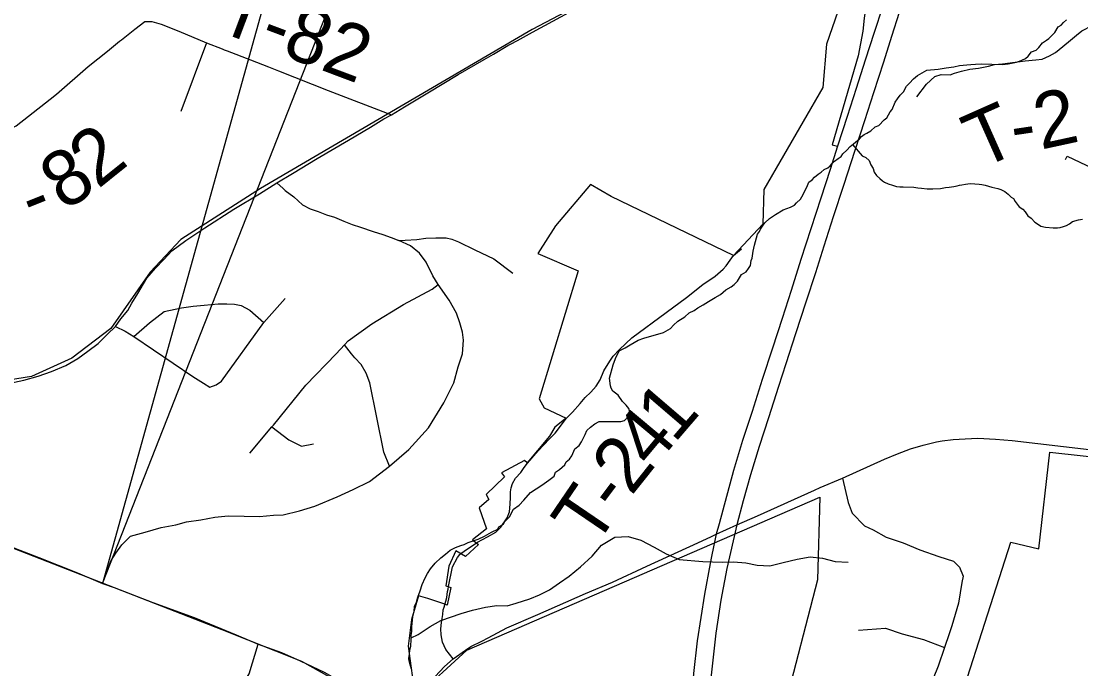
# Model space of a CAD drawing. Extents: x 44.2 to 78.2, y 4.5 to 26.5.
# Drawn here: x 50.025 to 51.106, y 21.825 to 22.487 of the extents above; entities that cross this region are included whole.
import ezdxf

# ---------------------------------------------------------------- set-up
doc = ezdxf.new("R2010")
doc.units = 0
for name, color, linetype in [('GM_X_City_Street', 7, 'Continuous'), ('GM_X_Corporation', 7, 'Continuous'), ('GM_X_Interchange_Ramps', 7, 'Continuous'), ('GM_X_Interstate_Route', 7, 'Continuous'), ('GM_X_Minor_River', 7, 'Continuous'), ('GM_X_Rail_Line', 7, 'Continuous'), ('GM_X_State_Route', 7, 'Continuous'), ('GM_X_Township_Road', 7, 'Continuous'), ('GM_X_Township_Road_Text', 7, 'Continuous'), ('GM_X_US_Route', 7, 'Continuous'), ('SH_Data', 7, 'Continuous')]:
    doc.layers.add(name, color=color, linetype=linetype)

msp = doc.modelspace()

# ---------------------------------------------------------------- linework, layer by layer
at = {"layer": 'GM_X_City_Street'}
for points in [[(50.2768, 22.4398), (50.2872, 22.4358), (50.3379, 22.4158), (50.4025, 22.3909)], [(50.2856, 22.3213), (50.2919, 22.3156), (50.2938, 22.3137), (50.3028, 22.3071), (50.3118, 22.299), (50.3195, 22.295), (50.3276, 22.2922), (50.336, 22.2887), (50.3442, 22.2863), (50.3539, 22.2824), (50.3622, 22.279), (50.371, 22.2761), (50.3837, 22.2719), (50.3938, 22.2686), (50.4023, 22.2655), (50.4098, 22.2624), (50.4163, 22.263), (50.4284, 22.2635), (50.4376, 22.265), (50.4476, 22.2654), (50.4583, 22.2652), (50.4639, 22.264), (50.4708, 22.2613), (50.4877, 22.253), (50.507, 22.2437), (50.5263, 22.2293)], [(50.1075, 21.9122), (50.1125, 21.9262), (50.1163, 21.9357), (50.121, 21.9433), (50.1271, 21.9517), (50.136, 21.9605), (50.1512, 21.9646), (50.1675, 21.9694), (50.1825, 21.9721), (50.1931, 21.9753), (50.2078, 21.9775), (50.2221, 21.9802), (50.2357, 21.9813), (50.252, 21.981), (50.2677, 21.9807), (50.2821, 21.9821), (50.2918, 21.9826), (50.3086, 21.9864), (50.3241, 21.9913), (50.3469, 22.0008), (50.3632, 22.0084), (50.38, 22.0165), (50.4006, 22.0323), (50.4201, 22.0491), (50.4402, 22.0713), (50.4559, 22.0968), (50.4662, 22.1174), (50.4705, 22.1337), (50.4749, 22.1467), (50.476, 22.1608), (50.4748, 22.1688), (50.4721, 22.1785), (50.4689, 22.1885), (50.4612, 22.2016), (50.4501, 22.2176), (50.4446, 22.2264), (50.438, 22.2405), (50.431, 22.2498), (50.422, 22.2572), (50.4098, 22.2624)], [(50.2579, 22.0454), (50.2804, 22.0722), (50.282, 22.0741), (50.3151, 22.1149), (50.3461, 22.147), (50.3544, 22.156), (50.3581, 22.16), (50.3823, 22.1774), (50.4149, 22.1973), (50.4441, 22.213), (50.4501, 22.2176)], [(50.1208, 22.1749), (50.1306, 22.17), (50.1394, 22.1644), (50.1996, 22.1238), (50.2107, 22.1168), (50.2169, 22.1128), (50.2234, 22.1152), (50.2291, 22.1191), (50.2721, 22.1788), (50.2938, 22.2035)], [(50.1394, 22.1644), (50.1556, 22.1785), (50.1703, 22.19), (50.1883, 22.1939), (50.2002, 22.1954), (50.2113, 22.1965), (50.2255, 22.1979), (50.2345, 22.198), (50.2423, 22.1975), (50.2492, 22.1962), (50.2578, 22.1915), (50.2721, 22.1788)], [(50.4006, 22.0323), (50.3947, 22.0464), (50.3803, 22.1172), (50.3766, 22.1271), (50.3715, 22.1359), (50.3649, 22.1428), (50.3616, 22.147), (50.3544, 22.156)], [(50.2804, 22.0722), (50.2976, 22.0589), (50.3106, 22.0526), (50.3229, 22.0551)], [(49.9347, 21.5938), (50.0348, 21.5782), (50.0794, 21.5705), (50.0896, 21.5691), (50.0905, 21.569), (50.1017, 21.5674), (50.1145, 21.5629), (50.1277, 21.5596), (50.1349, 21.558), (50.1386, 21.5575), (50.1403, 21.5581), (50.1425, 21.5609), (50.1729, 21.6564), (50.1975, 21.7476), (50.1999, 21.7516), (50.2077, 21.7606), (50.2286, 21.7815), (50.2449, 21.7994), (50.2571, 21.82), (50.2664, 21.8505)]]:
    msp.add_lwpolyline(points, dxfattribs=at)
at = {"layer": 'GM_X_Corporation'}
for points in [[(50.8722, 22.5379), (50.8465, 22.4631), (50.8426, 22.4188), (50.7826, 22.3148), (50.7814, 22.2792), (50.7514, 22.2471), (50.6267, 22.3074), (50.6057, 22.3197), (50.5699, 22.2775), (50.552, 22.2494), (50.5929, 22.2316), (50.5533, 22.1009), (50.5582, 22.0918), (50.5806, 22.0813), (50.5691, 22.072), (50.5637, 22.0628), (50.541, 22.0357), (50.5383, 22.0378), (50.5148, 22.0252), (50.5177, 22.0212), (50.499, 22.0033), (50.5018, 21.9981), (50.4921, 21.9896), (50.4994, 21.9682), (50.4851, 21.9569), (50.4914, 21.9523), (50.478, 21.9398), (50.468, 21.9458), (50.461, 21.93), (50.4578, 21.91), (50.463, 21.9081), (50.4593, 21.8903), (50.4568, 21.8912), (50.4397, 21.897), (50.4299, 21.8998), (50.423, 21.8756), (50.4195, 21.8483), (50.4265, 21.7958), (50.4793, 21.8443), (50.8396, 22.0004), (50.8373, 21.9161), (50.8031, 21.7833)], [(50.9609, 21.7244), (51.0348, 21.9545), (51.0631, 21.9476), (51.0744, 22.0465), (51.2726, 22.0245)]]:
    msp.add_lwpolyline(points, dxfattribs=at)
at = {"layer": 'GM_X_Interchange_Ramps'}
msp.add_lwpolyline([(50.8926, 22.6593), (50.896, 22.6522), (50.8986, 22.64), (50.8994, 22.6324), (50.9008, 22.6213), (50.9006, 22.6123), (50.8999, 22.6024), (50.8878, 22.5083), (50.8851, 22.4896), (50.8835, 22.4764), (50.8787, 22.4513), (50.8522, 22.3603), (50.8578, 22.3589)], dxfattribs=at)
at = {"layer": 'GM_X_Interstate_Route'}
msp.add_line((50.7332, 21.9596), (50.7291, 21.9398), dxfattribs=at)
for points in [[(50.9035, 22.5008), (50.8951, 22.4751), (50.8859, 22.4466), (50.8767, 22.4178), (50.8675, 22.3892), (50.8578, 22.3589)], [(50.9208, 22.4953), (50.9128, 22.4708), (50.9047, 22.4448), (50.8944, 22.4135), (50.8852, 22.3849), (50.8755, 22.3546), (50.864, 22.3187), (50.8534, 22.2869), (50.8439, 22.2568), (50.8352, 22.2297), (50.8254, 22.1997), (50.8149, 22.1672), (50.805, 22.1367), (50.7976, 22.1136), (50.7873, 22.0814), (50.7779, 22.0522), (50.769, 22.0233), (50.7613, 21.9967), (50.755, 21.9721), (50.7449, 21.9276), (50.7387, 21.8954), (50.7335, 21.8616), (50.7284, 21.8156)], [(50.8578, 22.3589), (50.8501, 22.3352), (50.8407, 22.3058), (50.8304, 22.2746), (50.8204, 22.243), (50.8103, 22.2114), (50.8011, 22.1828), (50.7914, 22.1525), (50.7809, 22.1205), (50.7706, 22.0879), (50.7609, 22.0582), (50.7516, 22.0278), (50.7406, 21.9873), (50.7368, 21.9733), (50.7338, 21.9626), (50.7332, 21.9596)], [(50.7291, 21.9398), (50.7276, 21.9329), (50.7218, 21.9016), (50.7144, 21.8538), (50.7109, 21.8205), (50.7081, 21.7852), (50.7061, 21.748), (50.7057, 21.6963), (50.706, 21.6768)]]:
    msp.add_lwpolyline(points, dxfattribs=at)
at = {"layer": 'GM_X_Minor_River'}
for points in [[(51.0884, 22.4851), (51.0915, 22.488)], [(50.6874, 22.1728), (50.6902, 22.1762), (50.6948, 22.1802), (50.7018, 22.1846), (50.7064, 22.1886), (50.7114, 22.1912), (50.7153, 22.1937), (50.7207, 22.197), (50.7261, 22.2003), (50.733, 22.2043), (50.7384, 22.2075), (50.7439, 22.2123), (50.7493, 22.2152), (50.7524, 22.2178), (50.7555, 22.2211), (50.7598, 22.2278), (50.7645, 22.2307), (50.7668, 22.2341), (50.7688, 22.2371), (50.7697, 22.242), (50.7705, 22.2446), (50.7715, 22.2518), (50.7723, 22.2548), (50.7731, 22.2578), (50.774, 22.2616), (50.7761, 22.2691), (50.778, 22.2717), (50.7792, 22.274), (50.7812, 22.2773), (50.7836, 22.2807), (50.7882, 22.2851), (50.7944, 22.2891), (50.8021, 22.2938), (50.8098, 22.2967), (50.814, 22.2985), (50.816, 22.3011), (50.8199, 22.3048), (50.8227, 22.3096), (50.8271, 22.3186), (50.8283, 22.322), (50.8318, 22.3245), (50.8341, 22.3271), (50.838, 22.3304), (50.8411, 22.3323), (50.8442, 22.3352), (50.8477, 22.3366), (50.8504, 22.3388), (50.8523, 22.3411), (50.8547, 22.3437), (50.8585, 22.3462), (50.8616, 22.3484), (50.8632, 22.351), (50.8671, 22.3547), (50.8706, 22.3584), (50.8741, 22.3614), (50.8803, 22.3665), (50.8823, 22.3687), (50.885, 22.3709), (50.8877, 22.372), (50.8919, 22.3745), (50.8962, 22.3786), (50.9, 22.38), (50.9055, 22.3859), (50.9082, 22.3878), (50.9114, 22.3938), (50.9134, 22.3964), (50.9166, 22.4039), (50.9189, 22.4072), (50.9217, 22.4109), (50.9252, 22.4143), (50.928, 22.4202), (50.9311, 22.4232), (50.9354, 22.4276), (50.9393, 22.4309), (50.9489, 22.4364), (50.9604, 22.4376), (50.9687, 22.4389), (50.9764, 22.4398), (50.9821, 22.4412), (50.9897, 22.4418), (50.9939, 22.4424), (50.9985, 22.4427), (51.0045, 22.4429), (51.0262, 22.4423), (51.0319, 22.4429), (51.0403, 22.4446), (51.0434, 22.4457), (51.046, 22.4467), (51.0495, 22.4485), (51.0522, 22.4507), (51.0558, 22.4552), (51.0604, 22.457), (51.0631, 22.4596), (51.067, 22.4644), (51.0709, 22.4673), (51.0736, 22.4688), (51.0763, 22.4714), (51.0794, 22.4751), (51.083, 22.4807), (51.0861, 22.4825), (51.0884, 22.4851)], [(50.8732, 22.3606), (50.8829, 22.349), (50.8867, 22.3474), (50.89, 22.3443), (50.8918, 22.34), (50.894, 22.3362), (50.895, 22.3324), (50.8976, 22.3289), (50.9009, 22.3258), (50.9035, 22.3234), (50.9058, 22.3222), (50.9095, 22.3206), (50.9137, 22.319), (50.9178, 22.3177), (50.9212, 22.3173), (50.9247, 22.3172), (50.9357, 22.3169), (50.9398, 22.3164), (50.9436, 22.3159), (50.9493, 22.3154), (50.955, 22.3153), (50.963, 22.3158), (50.9679, 22.3168), (50.9718, 22.3171), (50.9763, 22.3177), (50.9798, 22.3184), (50.9824, 22.3191), (50.9847, 22.3194), (50.9885, 22.3201), (50.9908, 22.3204), (50.9939, 22.3207), (50.998, 22.3206), (51.0022, 22.3201), (51.0049, 22.3196), (51.0083, 22.3192), (51.0154, 22.3171), (51.0215, 22.3158), (51.0245, 22.3146), (51.0286, 22.3126), (51.032, 22.3098), (51.0349, 22.3067), (51.0372, 22.3055), (51.039, 22.3024), (51.043, 22.297), (51.0468, 22.2947), (51.0494, 22.2919), (51.0519, 22.2877), (51.0553, 22.2853), (51.0593, 22.2814), (51.062, 22.2795), (51.0653, 22.2771), (51.0699, 22.2762), (51.0778, 22.2756), (51.0824, 22.2755), (51.085, 22.2758), (51.0885, 22.2769), (51.0915, 22.2779), (51.0946, 22.2797), (51.0977, 22.2819), (51.1038, 22.2837), (51.1077, 22.2843)], [(50.423, 21.8247), (50.4212, 21.8305), (50.4206, 21.8335), (50.4202, 21.8358), (50.4207, 21.8403), (50.4212, 21.8445), (50.4221, 21.8483), (50.4221, 21.8505), (50.4226, 21.8532), (50.4227, 21.8596), (50.4232, 21.8634), (50.4233, 21.8683), (50.4243, 21.8782), (50.4256, 21.8838), (50.4261, 21.8887), (50.4281, 21.8932), (50.4294, 21.8985), (50.4319, 21.9049), (50.4339, 21.9113), (50.4368, 21.9181), (50.4391, 21.9225), (50.4423, 21.9274), (50.447, 21.933), (50.4528, 21.9385), (50.4575, 21.9422), (50.4625, 21.9462), (50.4679, 21.9491), (50.4733, 21.9512), (50.4767, 21.9523), (50.4806, 21.9541), (50.4848, 21.9555), (50.4909, 21.9576), (50.4975, 21.9605), (50.5044, 21.9648), (50.5109, 21.9677), (50.5121, 21.9703), (50.5168, 21.9729), (50.518, 21.9755), (50.523, 21.9803), (50.527, 21.9881), (50.5328, 21.9922), (50.5375, 21.9973), (50.5442, 22.0051), (50.5561, 22.0128), (50.5631, 22.0179), (50.5685, 22.022), (50.5698, 22.0261), (50.574, 22.0286), (50.5794, 22.0334), (50.5807, 22.0364), (50.5842, 22.0394), (50.5865, 22.0427), (50.5897, 22.0498), (50.594, 22.0531), (50.5964, 22.0569), (50.6, 22.0644), (50.602, 22.0685), (50.6055, 22.0718), (50.6101, 22.0755), (50.6144, 22.0776), (50.6178, 22.0779), (50.6318, 22.0776), (50.6364, 22.0778), (50.6402, 22.0789), (50.6441, 22.0829), (50.645, 22.0856), (50.6454, 22.0886), (50.6447, 22.0909), (50.6421, 22.0944), (50.6381, 22.0983), (50.6337, 22.1048), (50.6284, 22.1088), (50.6266, 22.1118), (50.6259, 22.1141), (50.625, 22.1221), (50.6287, 22.1357), (50.6312, 22.1421), (50.6348, 22.1499), (50.641, 22.1528), (50.646, 22.1561), (50.6541, 22.1608), (50.6602, 22.1629), (50.6801, 22.1685), (50.6874, 22.1728)], [(50.4227, 21.8569), (50.4298, 21.8602), (50.4421, 21.8683), (50.4529, 21.8746), (50.4735, 21.8818), (50.485, 21.885), (50.4983, 21.8881), (50.5101, 21.8898), (50.5204, 21.8896), (50.5299, 21.8921), (50.5437, 21.8968), (50.5537, 21.9008), (50.5637, 21.9059), (50.5741, 21.9129), (50.5837, 21.9199), (50.5953, 21.9292), (50.6073, 21.9404), (50.617, 21.9516), (50.6305, 21.9597), (50.6442, 21.9602), (50.657, 21.9565), (50.6705, 21.9494), (50.6829, 21.9427), (50.6961, 21.9368), (50.7204, 21.9348), (50.7302, 21.9346), (50.7401, 21.934), (50.7515, 21.9345), (50.764, 21.9335), (50.7757, 21.931), (50.7886, 21.9304), (50.8024, 21.9339), (50.8165, 21.9371), (50.8299, 21.9395), (50.8424, 21.9381), (50.8552, 21.9348), (50.8685, 21.9342)]]:
    msp.add_lwpolyline(points, dxfattribs=at)
at = {"layer": 'GM_X_Rail_Line'}
for points in [[(51.1021, 22.7705), (50.546, 22.4779), (50.2689, 22.3155), (50.1875, 22.2635), (50.1561, 22.2304), (50.116, 22.1728), (50.0761, 22.1423), (50.0349, 22.1238), (49.6995, 22.0704), (49.4839, 22.0315), (49.4578, 22.0361), (49.4221, 22.0549), (49.3979, 22.0561), (49.3294, 22.0436), (49.3058, 22.0279), (49.275, 21.991), (49.1791, 21.7443), (49.1671, 21.738), (49.1375, 21.7503), (49.0811, 21.7307)], [(51.2918, 21.0838), (51.0931, 21.2312), (51.0625, 21.265), (50.9544, 21.4065), (50.9368, 21.4195), (50.8078, 21.4864), (50.7254, 21.5182), (50.6926, 21.5401), (50.5624, 21.6321), (50.4275, 21.7557), (50.3766, 21.7958), (50.3111, 21.8326), (50.2298, 21.8649), (49.7218, 22.0632), (49.7052, 22.0651), (49.4758, 22.027), (49.3978, 22.0023), (49.2916, 21.9373), (49.2761, 21.9016), (49.2584, 21.8511), (49.2022, 21.7058), (49.1723, 21.6528), (49.1425, 21.62), (49.1167, 21.5979)]]:
    msp.add_lwpolyline(points, dxfattribs=at)
at = {"layer": 'GM_X_State_Route'}
for points in [[(50.5311, 22.4669), (50.5463, 22.4753), (50.5671, 22.4866), (50.5836, 22.4953)], [(50.1376, 22.1986), (50.1434, 22.2086), (50.1529, 22.224), (50.1616, 22.2342), (50.1701, 22.243), (50.1782, 22.252), (50.1925, 22.2627), (50.2118, 22.2755), (50.2416, 22.2945), (50.2678, 22.3103), (50.2856, 22.3213), (50.3014, 22.331), (50.3267, 22.3463), (50.3586, 22.3651), (50.381, 22.3784), (50.3946, 22.3867), (50.4025, 22.3909), (50.4158, 22.399), (50.4396, 22.4133), (50.4705, 22.4321), (50.4971, 22.4474), (50.5066, 22.4529), (50.5213, 22.4616), (50.5239, 22.463), (50.5311, 22.4669)], [(49.9983, 22.114), (49.9992, 22.1142), (50.0081, 22.1159), (50.0272, 22.1199), (50.0417, 22.1241), (50.0555, 22.1287), (50.0701, 22.1348), (50.0824, 22.1421), (50.0925, 22.1494), (50.1032, 22.1575), (50.1126, 22.167), (50.1208, 22.1749), (50.1262, 22.1826), (50.1333, 22.1911), (50.1376, 22.1986)], [(50.8344, 22.0077), (50.8401, 22.0102), (50.8627, 22.02), (50.9058, 22.0393), (50.9191, 22.0447), (50.9324, 22.0497), (50.9453, 22.0536), (50.9589, 22.0571), (50.9645, 22.0579), (50.9759, 22.0593), (50.9882, 22.0599), (51.0008, 22.0606), (51.0191, 22.0596), (51.036, 22.0583), (51.1147, 22.049), (51.1524, 22.0443), (51.2018, 22.0382), (51.2488, 22.0328), (51.2962, 22.0268), (51.3161, 22.0246)], [(50.7292, 21.9604), (50.7338, 21.9626), (50.755, 21.9721), (50.7761, 21.9813), (50.8344, 22.0077)], [(50.6632, 21.9299), (50.7151, 21.954), (50.7292, 21.9604)], [(50.5011, 21.857), (50.5202, 21.867), (50.5519, 21.8808), (50.6005, 21.9022), (50.6282, 21.9137), (50.6632, 21.9299)], [(50.4655, 21.8353), (50.4779, 21.8442), (50.4835, 21.8479), (50.4948, 21.8536), (50.5011, 21.857)], [(50.4285, 21.7986), (50.4357, 21.8059), (50.4472, 21.8175), (50.4565, 21.8276), (50.4655, 21.8353)]]:
    msp.add_lwpolyline(points, dxfattribs=at)
at = {"layer": 'GM_X_Township_Road'}
msp.add_line((50.2135, 22.4645), (50.1874, 22.3942), dxfattribs=at)
for points in [[(50.0541, 22.4069), (50.0606, 22.4121), (50.0929, 22.4401), (50.1126, 22.456), (50.125, 22.466), (50.127, 22.4676), (50.1406, 22.4782), (50.1507, 22.4862), (50.1558, 22.4862), (50.1568, 22.4862)], [(50.1568, 22.4862), (50.1578, 22.4863), (50.1674, 22.4836), (50.1853, 22.4762)], [(50.9773, 22.4333), (50.9844, 22.4355), (50.9929, 22.4375), (51.0017, 22.4385), (51.0118, 22.4407), (51.0181, 22.4423), (51.0261, 22.4428), (51.0391, 22.4445), (51.0493, 22.446), (51.0602, 22.447), (51.0667, 22.4479), (51.0742, 22.4511), (51.0801, 22.4545), (51.0878, 22.4605), (51.0955, 22.4673), (51.1018, 22.4723), (51.1072, 22.4767), (51.1176, 22.4822), (51.1314, 22.4868)], [(50.1853, 22.4762), (50.2135, 22.4645), (50.2296, 22.4582), (50.2316, 22.4574)], [(50.2316, 22.4574), (50.2346, 22.4562), (50.2584, 22.447), (50.2768, 22.4398)], [(50.9388, 22.4091), (50.9486, 22.4222), (50.9571, 22.43), (50.9637, 22.432), (50.9726, 22.4319), (50.9773, 22.4333)], [(49.9658, 22.3606), (49.9903, 22.3682), (50.008, 22.3739), (50.0195, 22.3798), (50.0493, 22.403), (50.0541, 22.4069)], [(51.0906, 22.3452), (51.0923, 22.3488), (51.1115, 22.3395), (51.1582, 22.3168), (51.162, 22.3148), (51.1657, 22.3127), (51.1692, 22.3103), (51.1727, 22.3077), (51.1759, 22.3049), (51.1973, 22.2856), (51.2186, 22.2663), (51.2535, 22.2384), (51.2843, 22.2141), (51.2867, 22.2124), (51.2892, 22.2108), (51.2918, 22.2095), (51.2946, 22.2083), (51.2974, 22.2074), (51.3003, 22.2067), (51.3032, 22.2062), (51.3419, 22.2015), (51.3767, 22.1972)], [(50.7411, 22.2333), (50.7442, 22.2366), (50.7483, 22.2425), (50.7514, 22.2473), (50.7598, 22.2539)], [(50.5667, 22.063), (50.5694, 22.0657), (50.5751, 22.0731), (50.5809, 22.0808), (50.5874, 22.0874), (50.5951, 22.0961), (50.6003, 22.1021), (50.6059, 22.1078), (50.6114, 22.1138), (50.6156, 22.1202), (50.6191, 22.1295), (50.6253, 22.1395), (50.6289, 22.1445), (50.6353, 22.1512), (50.6479, 22.1632), (50.6828, 22.1891), (50.7036, 22.2045), (50.7204, 22.2176), (50.7329, 22.2263), (50.7411, 22.2333)], [(50.5291, 22.02), (50.5346, 22.0256), (50.538, 22.0307), (50.5413, 22.0352), (50.5521, 22.0479), (50.5634, 22.0597), (50.5667, 22.063)], [(50.488, 21.9529), (50.4904, 21.9544), (50.5004, 21.9601), (50.5091, 21.9647), (50.5142, 21.97), (50.5207, 21.9793), (50.523, 21.9855), (50.5235, 21.9934), (50.524, 22.0006), (50.524, 22.0058), (50.5246, 22.0099), (50.5259, 22.0144), (50.5291, 22.02)], [(50.8627, 22.02), (50.8686, 21.9949), (50.8726, 21.9841), (50.8853, 21.9711), (50.8941, 21.967), (50.9073, 21.9596), (50.9248, 21.9538), (50.9419, 21.9468), (50.9611, 21.94), (50.9762, 21.935), (50.9823, 21.9289), (50.986, 21.9199), (50.9847, 21.9133), (50.9811, 21.8921), (50.9745, 21.869), (50.9718, 21.861), (50.9671, 21.847), (50.9605, 21.8278), (50.9555, 21.8153)], [(50.4724, 21.9419), (50.473, 21.9426), (50.478, 21.9464), (50.488, 21.9529)], [(50.4602, 21.9067), (50.4606, 21.9092), (50.4646, 21.9293), (50.4699, 21.939), (50.4724, 21.9419)], [(50.4562, 21.8881), (50.457, 21.8907), (50.4588, 21.8981), (50.4598, 21.9041), (50.4602, 21.9067)], [(50.4655, 21.8353), (50.458, 21.8449), (50.4545, 21.8523), (50.4532, 21.8598), (50.4527, 21.8659), (50.4536, 21.8725), (50.4549, 21.8807), (50.4553, 21.8854), (50.4562, 21.8881)], [(50.8793, 21.8647), (50.9066, 21.8667), (50.9238, 21.861), (50.9456, 21.8553), (50.9671, 21.847)]]:
    msp.add_lwpolyline(points, dxfattribs=at)
at = {"layer": 'GM_X_US_Route'}
for points in [[(49.7056, 22.0687), (49.7556, 22.0488), (49.9133, 21.9888), (49.9972, 21.9561), (50.0424, 21.9389), (50.0819, 21.9231), (50.1075, 21.9122)], [(50.1075, 21.9122), (50.1193, 21.9083), (50.1589, 21.8928), (50.2012, 21.8776), (50.244, 21.8599), (50.2664, 21.8505), (50.2903, 21.8419), (50.2963, 21.8393)], [(50.2963, 21.8393), (50.3092, 21.8335), (50.3336, 21.8217), (50.3597, 21.8072), (50.3789, 21.7961), (50.4069, 21.775)]]:
    msp.add_lwpolyline(points, dxfattribs=at)
at = {"layer": 'SH_Data'}
msp.add_lwpolyline([(50.6141, 23.7345), (50.1075, 21.9122), (50.6141, 23.202)], close=True, dxfattribs=at)

# ---------------------------------------------------------------- texts
at = {"layer": 'GM_X_Township_Road_Text'}
for s, height, rotation, p in [('T-82', 0.05682, 339.387, (50.2219, 22.4776)), ('2', 0.0568, 12.2516, (51.0652, 22.3552)), ('T', 0.0568, 23.9538, (51.0031, 22.3349)), ('2', 0.0568, 38.7522, (50.1028, 22.3146)), ('-', 0.0568, 8.4458, (51.038, 22.3511)), ('8', 0.0568, 33.0613, (50.0685, 22.292)), ('-', 0.0568, 21.7496, (50.036, 22.2777)), ('1', 0.0568, 49.3462, (50.6911, 22.0547)), ('4', 0.0568, 50.0625, (50.6688, 22.0281)), ('2', 0.0568, 51.4678, (50.6472, 22.001)), ('T', 0.0568, 55.7453, (50.61, 21.948)), ('-', 0.0568, 53.2581, (50.6335, 21.9826))]:
    msp.add_text(s, height=height, rotation=rotation, dxfattribs=at).set_placement(p)

doc.saveas('drawing.dxf')
